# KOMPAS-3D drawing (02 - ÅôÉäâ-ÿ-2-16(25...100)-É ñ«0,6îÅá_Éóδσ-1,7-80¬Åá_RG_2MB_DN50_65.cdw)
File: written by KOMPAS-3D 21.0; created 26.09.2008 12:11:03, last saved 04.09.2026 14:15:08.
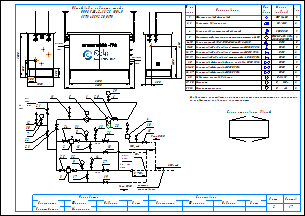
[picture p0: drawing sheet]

Sheets 1-2: A3, landscape

Document properties: Наименование: Макро:21; Автор: RaskoAdmin; Форматы листов документа: 2xA3; Полное имя файла: \\ur38nt01\Departments\КТО\КБ ПУРДГ\Заявки\Прайс-лист на типовые шкафы ГРПШ\ПУРДГ_стандарт_30_04_2026\ПУРДГ с RG_2MB\ПУРДГ-Ш-2-16(25...100)-Р до0,6МПа_Рвых-1,7-80кПа_RG_2MB_DN50_65.cdw

Title block, sheet 1: Наименование: Пункт учета газа / ПУГ-Ш-400-Р / ЛГТИ.485922.001ТУ; designation: ЛГТИ.03.4411141; sheet number: 1; Количество листов документа: 2; organisation: ООО "ЭЛЬСТЕР Газэлектроника"; Форматы листов документа: A3; stored path: C:\Рабочие документы\Компас\ПУГ\Схема.cdw; Разработал: Устинов; Проверил: Кошкин; Утвердил: Кошкин
Title block, sheet 2: sheet number: 2; stored path: D:\Рабочие документы\Заявки\ПУРДГ\ПУРДГ-ШУЭО-2-100-Р 4411220.cdw; designation, second copy: ЛГТИ.03.4411141-

Views: Вид 1, Вид 2
Referenced files: wcvoit.frw
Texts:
  Normal
  № на
  схеме
  Усл.
  обозн.
  Марка
  (модель)
  Кол.
  Фильтр газовый фланцевый
  ФГ 16-50
  Регулятор давления газа
  RG/2MB
  Клапан предохранительный сбросной
  КПС DN20
  Измерительный комплекс с ротационным счетчиком Ду50
  СГ-ЭК-Р-(0,2...2,0)-
  Кран кнопочный VE-РАСКО-НЗ-1,6-G1/2-М20
  DN15
  Кран шаровой "под приварку" штуцерный DN20 PN16
  DN20
  Кран шаровой "под приварку" штуцерный DN15 PN16
  Кран шаровой "под приварку" штуцерный п/п DN20 PN16
  Кран шаровой фланцевый с мех. приводом DN50 PN16
  Кран шаровой фланцевый DN50 PN16
  Кран шаровой фланцевый DN65 PN16
  DN50
  DN65
  Индикатор перепада давления
  Манометр
  Манометр-напоромер
  Delta 15
  0...     МПа
  0...     кПа
  Общий вид и габариты шкафа
  ПУРДГ-Ш-2-16(25...100)-Р
  Выход газа
  Вход газа
  logo-rasko-ge.png
  DN 1
  местное
  сопротивление
  Римп DN20
  Выход
  газа
  Р=     кПа
  Вход
  Р=       МПа
  PDI
  Схема открывания дверей
  Предприятие изготовитель может заменять комплектующие на аналогичные,
  не ухудшающие заявленных характеристик.
  Должность
  Конструктор
  Фамилия
  Подпись
  Дата
  Согласовано
  Максимкин
  Лист
  Листов
  POLYLINE_STYLE_0.18_RGB_0_0_0
  POLYLINE_STYLE_0.50_RGB_0_0_0
  POLYLINE_STYLE_0.34_RGB_0_0_0
  PHANTOM_RGB_0_0_0_SC_1_THICK_0.18
  K5LT_THIN_RGB_0_0_0_THICK_0.18
  K5LT32769_RGB_0_0_0_THICK_0.18
  K5LT12_RGB_0_0_0_SC_1_THICK_0.18
  K5LT_DASHED_RGB_0_0_0_SC_1_THICK_0.18
  ACISOTGL_RGB_0_0_0_SC_0.8_THICK_0.25
  CONTINUOUS_RGB_0_127_31_THICK_0.3
  CONTINUOUS_RGB_0_0_255_THICK_0.35
  CONTINUOUS_RGB_255_0_0_THICK_0.35
  POLYLINE_STYLE_0.25_RGB_0_0_0
  CONTINUOUS_RGB_0_0_0_THICK_0.5
  POLYLINE_STYLE_0.35_RGB_0_0_255
  CONTINUOUS_RGB_0_0_0_THICK_0.4
  CONTINUOUS_RGB_0_0_0_THICK_0.35
  НЕВИДИМАЯ_RGB_0_0_0_SC_0.3_THICK_0.25
  СONTINUOUS_RGB_0_0_0_THICK_0.25
  ОСЕВАЯ2_RGB_248_153_30_SC_0.3_THICK_0.25
  Без оформления
Dimensions and other numbers on the sheet: 1; 2, 3; 2; 4; 5; 6-10; 11-15; 16, 17; 18, 19; 20; 21-25; 26, 27; 28; 29, 30; 31, 32; 1500; 250; 300; 1050; 550; 305; 2300; 4130; 2000; 2600; 5,,,7DN 1; 7; 30; 12; 21; 22; 23; 11; 6; 29; 24; 31; 8; 16; 13; 26; 18; 10; 15; 25; 32; 9; 3; 17; 14; 27; 19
